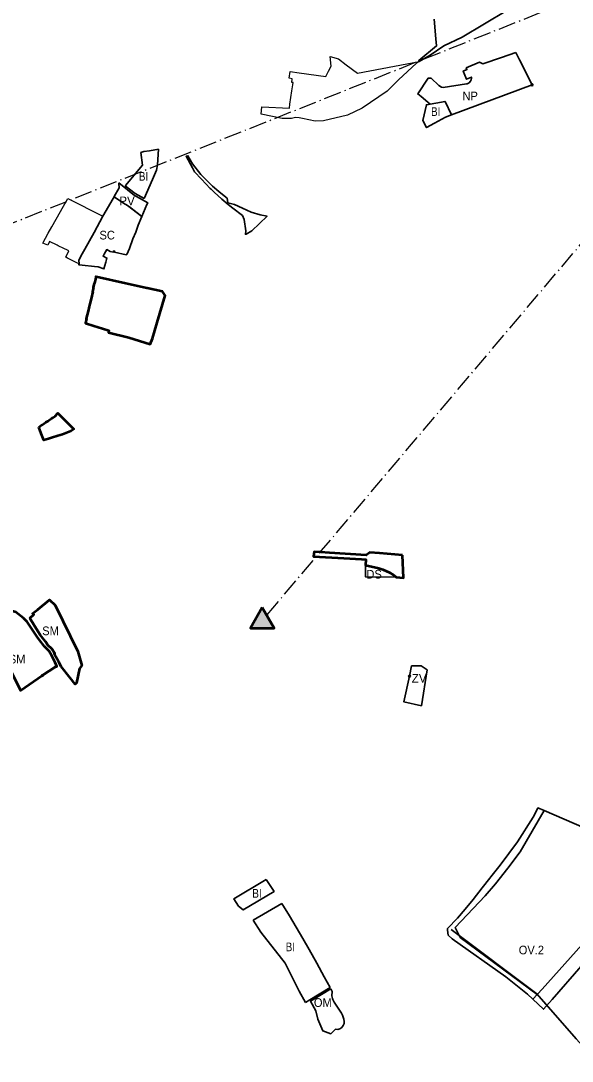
# Model space of a CAD drawing. Extents: x -650276 to -642489, y -1074311 to -1066658.
# Drawn here: x -646929 to -646170, y -1071706 to -1070271 of the extents above; entities that cross this region are included whole.
import ezdxf

# ---------------------------------------------------------------- set-up
doc = ezdxf.new("R2010")
doc.units = 0
doc.header["$LTSCALE"] = 4.8
doc.header["$PDMODE"] = 32
doc.header["$PDSIZE"] = 2.4
doc.linetypes.add('DOT_DASHED', pattern=[7.7, 5, -1.2, 0.3, -1.2])
for name, color, linetype, lineweight in [('11', 7, 'Continuous', 35), ('12', 7, 'Continuous', 35), ('15', 7, 'Continuous', 35), ('17', 7, 'Continuous', 35), ('18', 7, 'Continuous', 35), ('2', 7, 'Continuous', 35), ('24', 7, 'Continuous', 35), ('40', 7, 'Continuous', 35), ('48', 7, 'Continuous', 35), ('54', 7, 'Continuous', 35), ('55', 7, 'Continuous', 53), ('60', 7, 'Continuous', 53), ('61', 7, 'Continuous', 25)]:
    doc.layers.add(name, color=color, linetype=linetype, lineweight=lineweight)
doc.layers.add('62', color=7, linetype='Continuous')

msp = doc.modelspace()

# ---------------------------------------------------------------- hatches: boundary and pattern name
at = {"layer": '55'}
msp.add_hatch(color=256, dxfattribs=at).paths.add_polyline_path([(-646596.857, -1071079.969), (-646612.808, -1071108.615), (-646580.424, -1071108.615)])

# ---------------------------------------------------------------- linework, layer by layer
at = {"layer": '11'}
msp.add_lwpolyline([(-646066.165, -1071422.155), (-646153.5, -1071383.85), (-646208.577, -1071360.044), (-646241.68, -1071416.887), (-646258.487, -1071439.265), (-646275.615, -1071460.886), (-646289.976, -1071477.514), (-646330.914, -1071521.11), (-646324, -1071535), (-646217.978, -1071613.552), (-646211.407, -1071606.247), (-646156.471, -1071545.166), (-646094.063, -1071471.007)], close=True, dxfattribs=at)
at = {"layer": '12'}
msp.add_lwpolyline([(-646502.39, -1071605.72), (-646530.27, -1071622.79), (-646522.99, -1071636.22), (-646520.32, -1071647.59), (-646513.43, -1071663.64), (-646502.53, -1071667.82), (-646496.06, -1071661.5), (-646492.89, -1071661.75), (-646490.07, -1071660.88), (-646487.36, -1071659.1), (-646485.29, -1071656.53), (-646484.15, -1071653.38), (-646483.97, -1071650.63), (-646484.38, -1071647.41), (-646485.2, -1071644.85), (-646486.31, -1071641.97), (-646487.56, -1071639.23), (-646497.83, -1071624.02), (-646499.829, -1071620.704), (-646500.289, -1071619.291), (-646500.83, -1071615.62), (-646500.34, -1071609.66)], close=True, dxfattribs=at)
at = {"layer": '15'}
for points in [[(-646623.95, -1070529.36), (-646634.85, -1070524.43), (-646644.2, -1070522.08), (-646645.31, -1070515.85), (-646654, -1070509), (-646656.83, -1070506.66), (-646665.457, -1070499.019), (-646667.42, -1070497.28), (-646681.6, -1070482.89), (-646692.74, -1070468.28), (-646699.26, -1070457.2), (-646701.65, -1070457.93), (-646693.119, -1070474.009), (-646690.316, -1070479.212), (-646680.44, -1070489.669), (-646668.361, -1070502.459), (-646667.369, -1070503.36), (-646662.895, -1070507.428), (-646652.352, -1070517.013), (-646643.895, -1070524.284), (-646637.158, -1070529.564), (-646624.211, -1070539.711), (-646621.729, -1070545.248), (-646619.34, -1070560.95), (-646619.99, -1070565.54), (-646619.15, -1070565.53), (-646611.41, -1070560.96), (-646590.2, -1070540.66), (-646599.81, -1070538.51), (-646611.88, -1070534.82)], [(-646275.615, -1071460.886), (-646258.487, -1071439.265), (-646241.68, -1071416.887), (-646208.577, -1071360.044), (-646217.049, -1071356.382), (-646220.61, -1071363.16), (-646223.77, -1071369.24), (-646245.1, -1071403.04), (-646269.2, -1071435.22), (-646281.99, -1071451.4), (-646283.52, -1071453.34), (-646293.87, -1071466.43), (-646306.14, -1071482.86), (-646317.52, -1071496.12), (-646327.97, -1071508.29), (-646341.88, -1071522.81), (-646341.66, -1071524.87), (-646340.93, -1071531.64), (-646335.3, -1071537.05), (-646261.46, -1071589.38), (-646231.43, -1071613.06), (-646223.928, -1071620.168), (-646217.978, -1071613.552), (-646324, -1071535), (-646330.914, -1071521.11), (-646289.976, -1071477.514), (-646275.615, -1071460.886)]]:
    msp.add_lwpolyline(points, close=True, dxfattribs=at)
for points in [[(-646794.59, -1070494.62), (-646794.53, -1070495.7), (-646793.75, -1070501.26), (-646800.6, -1070513.43), (-646800.94, -1070514.04)], [(-646755.84, -1070524.5), (-646754.52, -1070522.08), (-646765.96, -1070515.75), (-646770.95, -1070512.94), (-646773, -1070511.96), (-646794.59, -1070494.62)], [(-646800.94, -1070514.04), (-646788, -1070522.49), (-646782.63, -1070526.02)], [(-646782.63, -1070526.02), (-646779.68, -1070527.87), (-646762.71, -1070540.85), (-646755.84, -1070524.5)], [(-646156.471, -1071545.166), (-646211.407, -1071606.247), (-646223.928, -1071620.168), (-646209.322, -1071634.004), (-646197.398, -1071620.579), (-646077.593, -1071482.499)]]:
    msp.add_lwpolyline(points, dxfattribs=at)
at = {"layer": '17'}
msp.add_lwpolyline([(-646802.19, -1070516.26), (-646816.42, -1070540.49), (-646828.45, -1070562.89), (-646841.16, -1070585.79), (-646844.76, -1070592.54), (-646849.72, -1070600.98), (-646848.99, -1070606.28), (-646849.59, -1070607.4), (-646844.96, -1070607.98), (-646827.88, -1070610.12), (-646822.99, -1070610.51), (-646815.05, -1070613.14), (-646812.5, -1070603.78), (-646811.5, -1070600.29), (-646810.82, -1070598.23), (-646816.11, -1070595.8), (-646814.52, -1070592.78), (-646811.06, -1070586.67), (-646806.41, -1070589), (-646802.06, -1070589.93), (-646801.73, -1070588.37), (-646800.13, -1070588.71), (-646800.47, -1070590.28), (-646784.18, -1070593.76), (-646784, -1070593.34), (-646783.59, -1070593.52), (-646779.9, -1070584.92), (-646774.91, -1070571.88), (-646771.17, -1070562.7), (-646767.63, -1070553.09), (-646762.71, -1070540.85), (-646782.63, -1070526.02), (-646788, -1070522.49), (-646800.94, -1070514.04)], close=True, dxfattribs=at)
at = {"layer": '18'}
for points in [[(-646881.89, -1071077.03), (-646890.12, -1071069.67), (-646913.49, -1071088.22), (-646911.58, -1071089.9), (-646917.04, -1071094.75), (-646910.53, -1071105.18), (-646902.62, -1071117.58), (-646895.56, -1071126.84), (-646892.339, -1071131.481), (-646886.78, -1071137.25), (-646882.37, -1071143.39), (-646883.63, -1071144.15), (-646873.89, -1071161.58), (-646861.58, -1071177.05), (-646854.49, -1071185.87), (-646852.86, -1071183.98), (-646848.58, -1071163.95), (-646845.39, -1071159.98), (-646850.93, -1071140.54)], [(-646955.39, -1071103.23), (-646949.12, -1071111.22), (-646957.26, -1071115.61), (-646960.72, -1071117.25), (-646964.99, -1071123.18), (-646964.43, -1071125.3), (-646955.2, -1071143.67), (-646929.64, -1071194.58), (-646899.85, -1071173.89), (-646881.68, -1071161.83), (-646879.91, -1071161.24), (-646881.97, -1071155.84), (-646887.07, -1071145.66), (-646890.59, -1071140.39), (-646896.62, -1071133.93), (-646904.64, -1071123.54), (-646906.72, -1071120.46), (-646920.54, -1071099.98), (-646925.88, -1071094.68), (-646936.51, -1071086.33), (-646940.67, -1071085.15), (-646943.47, -1071088.69)]]:
    msp.add_lwpolyline(points, close=True, dxfattribs=at)
msp.add_point((-646899.85, -1071173.89), dxfattribs=at)
at = {"layer": '2'}
msp.add_line((-646609.21, -1071510.98), (-646570, -1071488.38), dxfattribs=at)
for points in [[(-646344.93, -1070382.33), (-646336.25, -1070400.875), (-646344.26, -1070403.84), (-646359.769, -1070412.361), (-646370.56, -1070418.29), (-646375.63, -1070408.76), (-646370.624, -1070386.792)], [(-646591.65, -1071454.91), (-646635.79, -1071481.6), (-646629.37, -1071491.74), (-646623.18, -1071496.99), (-646580.58, -1071471.48)]]:
    msp.add_lwpolyline(points, close=True, dxfattribs=at)
for points in [[(-646739.74, -1070447.98), (-646752.29, -1070450.28), (-646760.03, -1070451.56), (-646763.94, -1070452.95), (-646761.8, -1070470.4), (-646785.15, -1070498.05), (-646785.5, -1070498.47)], [(-646759.42, -1070516.37), (-646747.89, -1070489.87), (-646742.37, -1070477.2), (-646741.33, -1070469.79), (-646739.74, -1070447.98)], [(-646785.5, -1070498.47), (-646771.9, -1070509.4), (-646759.42, -1070516.37)], [(-646570, -1071488.38), (-646559.53, -1071505.12), (-646550.23, -1071520.88), (-646541.14, -1071536.3), (-646532.04, -1071551.72), (-646521.8, -1071570.34), (-646511.47, -1071589.11), (-646503.31, -1071603.95), (-646531.2, -1071621.07), (-646537.28, -1071624.8)], [(-646537.28, -1071624.8), (-646545.89, -1071609.07), (-646555.78, -1071589.66), (-646565.17, -1071570.4), (-646598.63, -1071527.8), (-646609.21, -1071510.98)]]:
    msp.add_lwpolyline(points, dxfattribs=at)
at = {"layer": '24'}
msp.add_lwpolyline([(-646454.59, -1071021.54), (-646454.59, -1071038), (-646412.54, -1071038.01), (-646415.61, -1071035.4), (-646421.58, -1071031.81), (-646430.91, -1071027.44)], close=True, dxfattribs=at)
at = {"layer": '40'}
for points in [[(-646377.5, -1071215.56), (-646369.76, -1071166.06), (-646377.87, -1071160.66), (-646391.07, -1071160.52), (-646394.05, -1071174.83)], [(-646394.05, -1071174.83), (-646401.64, -1071210.18), (-646377.5, -1071215.56)]]:
    msp.add_lwpolyline(points, dxfattribs=at)
msp.add_point((-646394.05, -1071174.83), dxfattribs=at)
at = {"layer": '48'}
msp.add_lwpolyline([(-646359.89, -1070269.01), (-646357.73, -1070296.13), (-646356.8, -1070305.73), (-646381.25, -1070325.85), (-646380.69, -1070327.47), (-646365.63, -1070318.37), (-646346.57, -1070305.88), (-646321.24, -1070293.85), (-646259.91, -1070256.89)], dxfattribs=at)
msp.add_lwpolyline([(-646247.667, -1070315.004), (-646267.3, -1070321.61), (-646293.14, -1070330.3), (-646297.4, -1070328.01), (-646315.84, -1070336.13), (-646314.84, -1070338.41), (-646319.95, -1070340.42), (-646315.46, -1070351.67), (-646308.791, -1070348.855), (-646308.59, -1070350.22), (-646309.18, -1070352.77), (-646309.99, -1070354.58), (-646311.82, -1070356.89), (-646314.6, -1070358.05), (-646315.7, -1070358.27), (-646347.49, -1070363.01), (-646349.76, -1070362.69), (-646353.81, -1070360.18), (-646364.34, -1070350.19), (-646368.4, -1070350.41), (-646382.67, -1070371.94), (-646377.86, -1070375.71), (-646365.7, -1070385.89), (-646344.93, -1070382.33), (-646336.35, -1070400.9), (-646225.15, -1070359.46), (-646242.56, -1070325.1)], close=True, dxfattribs=at)
msp.add_point((-646225.15, -1070359.46), dxfattribs=at)
at = {"layer": '54'}
msp.add_lwpolyline([(-646336.784, -1071524.232), (-646218.737, -1071612.767), (-646164.374, -1071674.897), (-645904.456, -1071961.331), (-645718.199, -1072151.712), (-645526.944, -1072343.922), (-645538, -1072384), (-645459, -1072440), (-645389, -1072483), (-645335, -1072526), (-645287, -1072569), (-645227, -1072617), (-645139.573, -1072694.628), (-645084.365, -1072788.086)], dxfattribs=at)
at = {"layer": '55', "linetype": 'DOT_DASHED', "lineweight": 25}
for p, q in [((-647060.176, -1070597.455), (-645765.418, -1070080.935)), ((-646590, -1071090), (-645744.292, -1070089.84))]:
    msp.add_line(p, q, dxfattribs=at)
at = {"layer": '55'}
msp.add_lwpolyline([(-646596.857, -1071079.969), (-646612.808, -1071108.615), (-646580.424, -1071108.615)], close=True, dxfattribs=at)
at = {"layer": '60'}
for points in [[(-646825.54, -1070624.03), (-646826.12, -1070623.9), (-646826.45, -1070627.3), (-646827.98, -1070632.83), (-646828.22, -1070632.77), (-646829.55, -1070638.78), (-646829.55, -1070638.78), (-646829.3, -1070638.83), (-646830.51, -1070644.3), (-646830.26, -1070644.35), (-646832.46, -1070654.31), (-646832.7, -1070654.26), (-646834.27, -1070661.39), (-646834.27, -1070661.39), (-646834.4, -1070661.35), (-646835.23, -1070665.08), (-646835.1, -1070665.12), (-646836.6, -1070671.54), (-646836.6, -1070671.54), (-646836.87, -1070671.46), (-646839.27, -1070681.62), (-646838.96, -1070681.72), (-646840.36, -1070687.86), (-646828.7, -1070691.73), (-646816.84, -1070695.43), (-646808.09, -1070698.19), (-646808.76, -1070701.11), (-646780.44, -1070707.59), (-646751.23, -1070717), (-646748.04, -1070709.23), (-646741.52, -1070687.22), (-646730.66, -1070650.07), (-646734.18, -1070644.6), (-646755.21, -1070639.87), (-646755.84, -1070639.88), (-646784.62, -1070633.19)], [(-646904.8, -1070831.23), (-646900.57, -1070828.42), (-646900.09, -1070828.1), (-646897.34, -1070826.28), (-646894.84, -1070824.62), (-646892.34, -1070822.96), (-646889.85, -1070821.3), (-646887.3, -1070819.61), (-646884.68, -1070817.87), (-646882.18, -1070816.21), (-646878.66, -1070812.72), (-646878.61, -1070812.14), (-646862.56, -1070828.29), (-646856.41, -1070834.13), (-646860.55, -1070836.71), (-646871.78, -1070841.33), (-646875.05, -1070842.32), (-646878.26, -1070843.29), (-646881.11, -1070844.21), (-646884.27, -1070845.17), (-646887.32, -1070846.14), (-646891.42, -1070847.44), (-646897.71, -1070849.39), (-646901.26, -1070840.31)], [(-646403.81, -1071007.7), (-646435.28, -1071005.2), (-646448.48, -1071004.25), (-646453.7, -1071007.79), (-646504.25, -1071004.54), (-646516.78, -1071003.78), (-646525.4, -1071003.29), (-646526.31, -1071009.55), (-646484.27, -1071012.11), (-646460.09, -1071013.61), (-646454.02, -1071013.98), (-646454.59, -1071021.54), (-646436.15, -1071025.97), (-646430.91, -1071027.44), (-646421.58, -1071031.81), (-646415.61, -1071035.4), (-646412.54, -1071038.01), (-646402.09, -1071038.95)], [(-646917.04, -1071094.75), (-646911.58, -1071089.9), (-646913.49, -1071088.22), (-646906.17, -1071082.72), (-646890.12, -1071069.67), (-646881.89, -1071077.03), (-646850.93, -1071140.54), (-646845.39, -1071159.98), (-646848.58, -1071163.95), (-646852.86, -1071183.98), (-646854.49, -1071185.87), (-646861.58, -1071177.05), (-646873.89, -1071161.58), (-646877.226, -1071155.611), (-646883.63, -1071144.15), (-646882.37, -1071143.39), (-646886.78, -1071137.25), (-646892.11, -1071131.81), (-646895.56, -1071126.84), (-646902.62, -1071117.58), (-646910.53, -1071105.18)], [(-646955.39, -1071103.23), (-646949.12, -1071111.22), (-646957.26, -1071115.61), (-646960.72, -1071117.25), (-646964.99, -1071123.18), (-646964.43, -1071125.3), (-646955.2, -1071143.67), (-646929.64, -1071194.58), (-646899.85, -1071173.89), (-646881.68, -1071161.83), (-646879.91, -1071161.24), (-646881.97, -1071155.84), (-646887.07, -1071145.66), (-646890.59, -1071140.39), (-646896.62, -1071133.93), (-646904.64, -1071123.54), (-646906.72, -1071120.46), (-646920.54, -1071099.98), (-646925.88, -1071094.68), (-646936.51, -1071086.33), (-646940.67, -1071085.15), (-646943.47, -1071088.69)]]:
    msp.add_lwpolyline(points, close=True, dxfattribs=at)
at = {"layer": '61'}
for points in [[(-646503.36, -1070320.39), (-646491.81, -1070323.54), (-646481.1, -1070331.76), (-646465.85, -1070343.46), (-646380.69, -1070327.47), (-646384.18, -1070329.58), (-646408.97, -1070352.57), (-646422.07, -1070365.6), (-646424.74, -1070368.25), (-646459.18, -1070391.48), (-646479.26, -1070401.17), (-646512.38, -1070409.18), (-646523.89, -1070409.54), (-646541.25, -1070406.02), (-646545.97, -1070405.06), (-646550.91, -1070404.27), (-646556.66, -1070406.07), (-646569.39, -1070406.06), (-646598.16, -1070399.848), (-646597.44, -1070389.891), (-646559.41, -1070391.82), (-646558.74, -1070386.15), (-646556, -1070367.59), (-646554.86, -1070359.63), (-646554.86, -1070359.63), (-646554.42, -1070356.22), (-646556.1, -1070356), (-646555.42, -1070350.94), (-646559.71, -1070350.35), (-646558.49, -1070340.9), (-646545.77, -1070342.7), (-646509.08, -1070347.79), (-646505.44, -1070340.51), (-646501.94, -1070333.51)], [(-646867.54, -1070597.11), (-646863.26, -1070588.3), (-646872.19, -1070583.97), (-646876.02, -1070582.12), (-646877.88, -1070581.22), (-646879.541, -1070580.417), (-646889.9, -1070575.41), (-646892.4, -1070580.64), (-646899.2, -1070577.61), (-646891.65, -1070564.15), (-646886.72, -1070555.37), (-646864.73, -1070516.2), (-646816.66, -1070540.37), (-646816.42, -1070540.49), (-646828.45, -1070562.89), (-646838.95, -1070581.53), (-646841.16, -1070585.79), (-646844.76, -1070592.54), (-646849.72, -1070600.98), (-646849.72, -1070600.98), (-646848.99, -1070606.28), (-646852.3, -1070604.63), (-646859.48, -1070601.1), (-646865.02, -1070598.34)]]:
    msp.add_lwpolyline(points, close=True, dxfattribs=at)

# ---------------------------------------------------------------- texts
at = {"layer": '62'}
for s, width, p in [('NP', 0.95, (-646320.99, -1070380.819)), ('BI', 0.85, (-646364.337, -1070402.32)), ('BI', 0.85, (-646766.828, -1070491.569)), ('SC', 0.95, (-646821.06, -1070572.645)), ('DS', 0.95, (-646453.386, -1071040.148)), ('SM', 0.95, (-646899.938, -1071118.245)), ('SM', 0.95, (-646945.938, -1071157.245)), ('BI', 0.85, (-646610.515, -1071480.22)), ('BI', 0.85, (-646564.529, -1071553.971)), ('OV.2', 0.95, (-646243.486, -1071558.306)), ('OM', 0.95, (-646525.703, -1071630.756))]:
    msp.add_text(s, height=12, dxfattribs=dict(at, width=width)).set_placement(p)
for s, p in [('PV', (-646793.831, -1070525.433)), ('ZV', (-646390.931, -1071183.591))]:
    msp.add_text(s, height=12, dxfattribs=at).set_placement(p)

doc.saveas('drawing.dxf')
